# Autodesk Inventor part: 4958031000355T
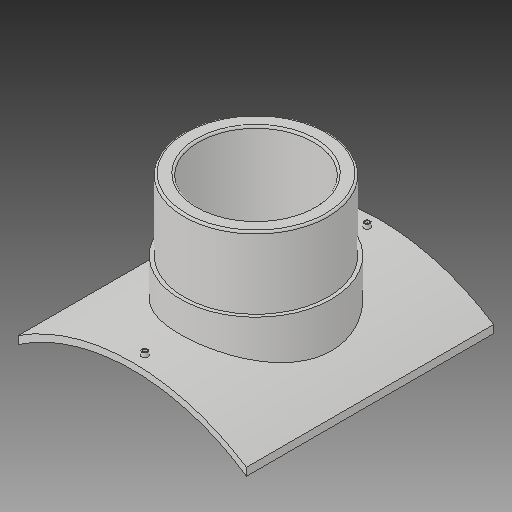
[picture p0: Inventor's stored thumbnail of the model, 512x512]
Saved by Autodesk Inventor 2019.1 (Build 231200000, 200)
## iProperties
Created: 2017-10
Part Number: 4958031000355T
Material: Generic
Description: PLASSON BRANCH SADDLE  1000x355
Document SubType Name: Modeling
Designer: KIM
Mass: 2754.05 g
Surface Area: 3037.44 cm^2
Volume: 2754.05 cm^3
Density: 1 g/cm^3
Appearance: Default
Author: KIM
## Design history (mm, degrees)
derived "495803.ipt"
feature "Solid1::495803.ipt"
tag "TaggingFeature1"
body "Solid1"
other parameters: "d1" = 16, "d2" = 563, "d4" = 0, "d12" = 525.6, "d13" = 14, "d14" = 274.5, "d16" = 5 deg, "d18" = 4, "d19" = 14, "d20" = 0, "d21" = 3, "d22" = 0, "d23" = 768, "d24" = 372.75, "d25" = 16, "d26" = 284, "d28" = 0, "d29" = 9.6, "d31" = 0, "d32" = 126, "d33" = 0, "d36" = 355, "d37" = 176.4, "d38" = 0, "d39" = 5, "d_1" = 355, "B_" = 563, "H_" = 252, "x_" = 16, "D_" = 16
